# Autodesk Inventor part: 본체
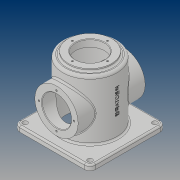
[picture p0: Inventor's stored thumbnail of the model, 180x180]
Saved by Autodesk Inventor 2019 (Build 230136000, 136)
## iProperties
Created: 2019-03
Part Number: 본체
Material: 일반
Document SubType Name: Modeling
Designer: PC312-16
Density: 1 g/cm^3
Appearance: 기본값
Author: PC312-16
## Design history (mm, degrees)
sketch "스케치1"
  geometry: L1 (0, 0)-(110, 0); L2 (102, 0)-(102, -45); L3 (102, -45)-(0, -45); L4 (0, -50)-(110, -50); L5 (110, -50)-(110, 0); L6 (0, -45)-(0, -50)
  constraints: 13 end point, 3 horizontal, 3 vertical, 2 point on line
  dimensions: "d0" = 110 distance of L1.start L1.end; "d1" = 100 diameter of L4 L1; "d3" = 90 diameter of L3 L1; "d4" = 8 distance of L1.end L2.start
revolve "회전1" sketch "스케치1" stored, may be unused: angle "d5" = 90 deg
sketch "스케치2"
  geometry: C1 r 40 at (0, 0); 1 further point
  constraints: 1 centre point, 1 coincident
  dimensions: "d6" = 80 diameter of C1
extrude "돌출1" join sketch "스케치2" distance "d7" = 5; taper "d8" = 0 deg
sketch "스케치3"
  geometry: C1 r 27 at (0, 0); 1 further point
  constraints: 1 centre point, 1 coincident
  dimensions: "d9" = 54 diameter of C1
extrude "돌출2" cut sketch "스케치3" distance "d10" = 13; taper "d11" = 0 deg
sketch "스케치4"
  geometry: L1 (70, 70)-(-70, 70); L2 (-70, 70)-(-70, -70); L3 (-70, -70)-(70, -70); L4 (70, -70)-(70, 70); L5 (70, 70)-(-70, -70); L6 (-70, 70)-(70, -70); C1 r 50 at (0, 0) reference; C2 r 50 at (0, 0) reference; C3 r 45 at (0, 0) reference; 1 further point
  constraints: 12 end point, 2 midpoint, 2 parallel, 1 horizontal, 1 perpendicular
  dimensions: "d12" = 140 distance of L3.end L2.end; "d13" = 140 distance of L2.end L1.end
extrude "돌출4" join sketch "스케치4" distance "d16" = 10; taper "d17" = 0 deg
node "작업 평면1"
sketch "스케치5"
  geometry: L1 (70, -10)-(-70, -10) reference; C1 r 40 at (0, 50); 2 further points
  constraints: 1 centre point, 1 midpoint, 1 vertical alignment
  dimensions: "d19" = 80 diameter of C1; "d20" = 60 distance from line of L1 C1.centre
extrude "돌출5" join sketch "스케치5" stored distance "d21" = 10; taper "d22" = 0 deg
fillet "모깎기1" dims "d23" = 3
sketch "스케치6"
  geometry: C1 r 40 at (0, 0) reference; 2 further points
  constraints: 1 vertical alignment
  dimensions: "d24" = 32.5 distance of C1.centre point (0, 32.5)
hole "구멍1" sketch "스케치6" at (0, 32.5) diameter "d25" = 3.242; stored, may be unused: countersink angle "d29" = 90 deg, drill point angle "d31" = 118 deg; dims "d26" = 8, "d27" = 4, "d28" = 2, "d30" = 10
sketch "스케치7"
  geometry: C1 r 40 at (0, 0) reference; C2 r 27 at (0, 0); 1 further point
  constraints: 1 centre point, 1 coincident
  dimensions: "d35" = 54 diameter of C2
extrude "돌출6" cut sketch "스케치7" extent not by distance; stored distance "d36" = 0; taper "d37" = 0 deg
sketch "스케치8"
  geometry: 2 further points
  constraints: 1 vertical alignment
  dimensions: "d38" = 32.5 distance of point (0, 0) point (0, 32.5)
hole "구멍2" sketch "스케치8" at (0, 32.5) diameter "d39" = 3.242; stored, may be unused: countersink angle "d43" = 90 deg, drill point angle "d45" = 118 deg; dims "d40" = 8, "d41" = 4, "d42" = 2, "d44" = 10
fillet "모깎기2" dims "d49" = 10
sketch "스케치9"
  geometry: C1 r 4.5 at (60, 60); A1 r 10 centre (60, 60) between (70, 60) and (60, 70) reference; 1 further point
  constraints: 1 centre point, 1 coincident
  dimensions: "d50" = 9 diameter of C1
extrude "돌출7" cut sketch "스케치9" extent not by distance; stored distance "d51" = 10; taper "d52" = 0 deg
fillet "모깎기3" dims "d59" = 5
fillet "모깎기4" dims "d60" = 3
fillet "모깎기5" dims "d61" = 3
chamfer "모따기1" distance "d62" = 1; stored, may be unused: second distance "d63" = 2, angle "d64" = 45 deg
fillet "모깎기6" dims "d65" = 3
node "작업 평면2"
sketch "스케치10"
  geometry: L1 (-10, -60)-(-10, 60) reference; 2 further points
  constraints: 1 horizontal alignment, 1 other
  dimensions: "d68" = 70 distance from line of L1 point (60, 0)
feature "엠보싱1" sketch "스케치10" dims "d69" = 0.5, "d70" = 0
node "솔리드1"
pattern_circular "원형 패턴1" dims angle "d33" = 360 deg
mirror "미러1"
pattern_circular "원형 패턴2" dims angle "d47" = 360 deg
pattern_linear "직사각형 패턴1" dims "d55" = 120, "d58" = 120
node "투영된 루프1"
other parameters: "d18" = 62
